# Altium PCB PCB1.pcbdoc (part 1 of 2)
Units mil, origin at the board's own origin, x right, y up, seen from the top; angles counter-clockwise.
Board outline 7352.2 x 4397.09 mil, 2 copper layers (Top Layer, Bottom Layer); 16 components, 5 nets, 164 pads, 4 vias.
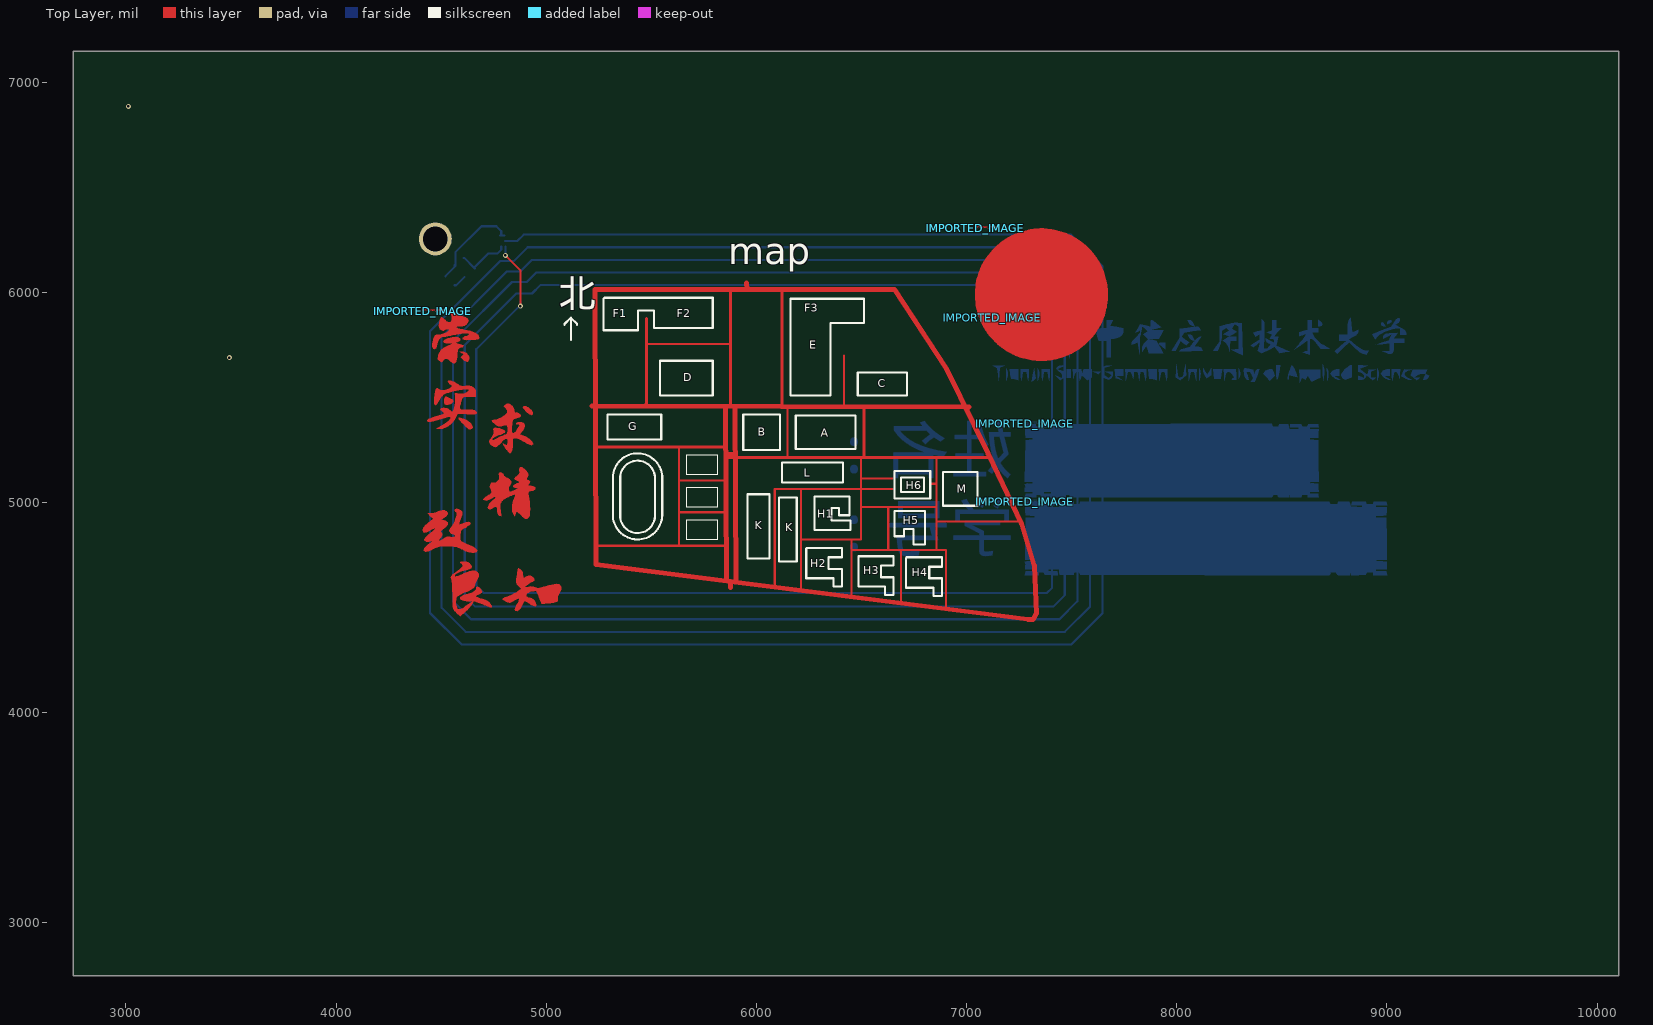
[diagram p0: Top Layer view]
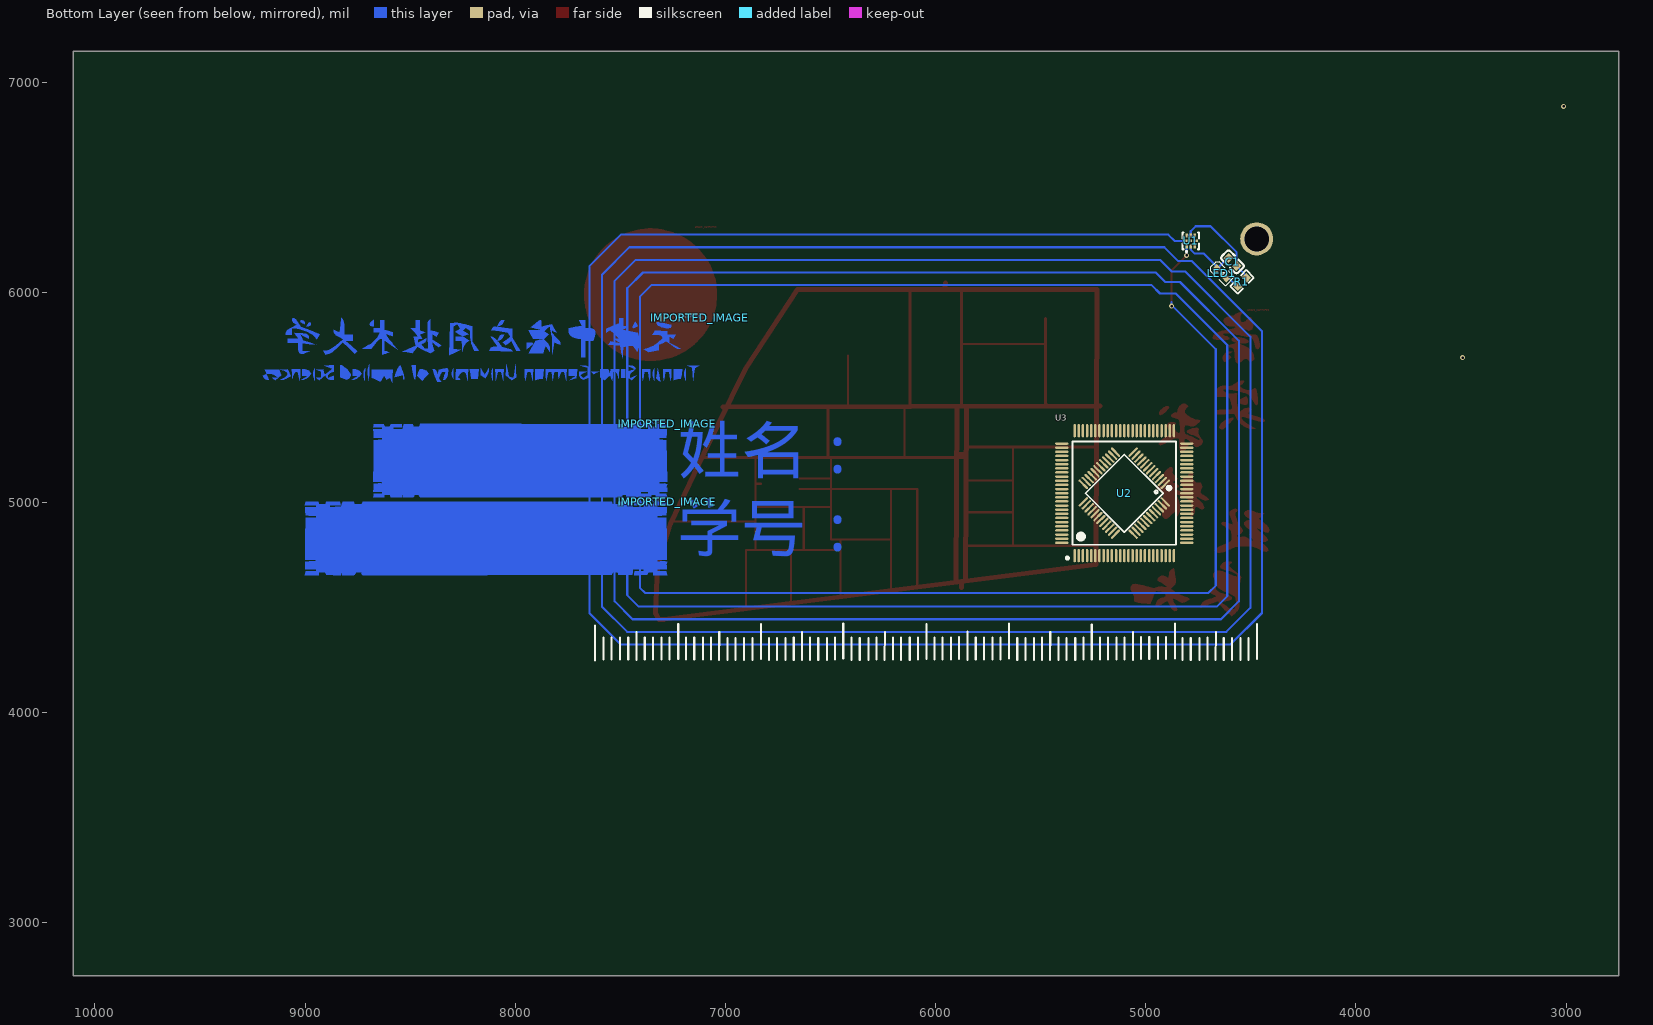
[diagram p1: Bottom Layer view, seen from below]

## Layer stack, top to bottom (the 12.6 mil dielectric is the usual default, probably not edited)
Top Solder: solder mask 0.4, Solder Resist, Dk 3.5
Top Layer: signal copper 1.4
Dielectric 1: dielectric 12.6, FR-4, Dk 4.8
Bottom Layer: signal copper 1.4
Bottom Solder: solder mask 0.4, Solder Resist, Dk 3.5

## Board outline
10102.2,2750 2750,2750 2750,7147.09 10102.2,7147.09

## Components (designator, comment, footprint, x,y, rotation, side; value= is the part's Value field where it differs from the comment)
C1 "100nF" C0603 4587.01,6145.08 r225 bottom
IMPORTED_IMAGE "IMPORTED_IMAGE" IMPORTED_IMAGE#1 7277.01,5005.08 r0 top
IMPORTED_IMAGE "IMPORTED_IMAGE" IMPORTED_IMAGE#1 4412.01,5910.08 r0 top
IMPORTED_IMAGE "IMPORTED_IMAGE" IMPORTED_IMAGE#2 4412.01,5910.08 r0 top
IMPORTED_IMAGE "IMPORTED_IMAGE" IMPORTED_IMAGE#3 7277.01,5005.08 r0 bottom
IMPORTED_IMAGE "IMPORTED_IMAGE" IMPORTED_IMAGE#4 7042.01,6305.08 r0 top
IMPORTED_IMAGE "IMPORTED_IMAGE" IMPORTED_IMAGE#1 7042.01,6305.08 r0 top
IMPORTED_IMAGE "IMPORTED_IMAGE" IMPORTED_IMAGE#5 7122.01,5880.08 r0 bottom
IMPORTED_IMAGE "IMPORTED_IMAGE" IMPORTED_IMAGE#1 7122.01,5880.08 r0 top
IMPORTED_IMAGE "IMPORTED_IMAGE" IMPORTED_IMAGE#6 7277.01,5375.08 r0 bottom
IMPORTED_IMAGE "IMPORTED_IMAGE" IMPORTED_IMAGE#1 7277.01,5375.08 r0 top
LED1 "LED_0603-R" LED_0603 4637.01,6090.08 r225 bottom
R1 "100" R0603 4542.01,6050.08 r315 bottom
U1 "NT3H1101W0FHKH" XQFN-8_L1.6-W1.6-P0.50-BR 4785.63,6245.08 r270 bottom
U2 "STM32F103C8T6" LQFP-48_L7.0-W7.0-P0.50-LS9.0-BL 5102.01,5045.08 r45 bottom
U3 "STM32F103VET6" LQFP-100_L14.0-W14.0-P0.50-LS16.0-BL 5102,5045.08 r180 bottom

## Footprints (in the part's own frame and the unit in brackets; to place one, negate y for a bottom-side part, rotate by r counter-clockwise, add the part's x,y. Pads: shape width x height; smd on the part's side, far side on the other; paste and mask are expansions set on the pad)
C0603 [mm]
  rect 0.8x0.9 smd: 1(-0.7,0) 2(0.7,0)
  silkscreen extent -1.41,-0.71 1.39,0.72
IMPORTED_IMAGE#1 [mil]
IMPORTED_IMAGE#2 [mil]
  Top Layer region: 241 vertices and 2 holes, not listed, extent 134.67,-1450 328.29,-1191.69
  Top Layer region: 207 vertices and 1 holes, not listed, extent 379.28,-1426.39 660.32,-1223.11
  Top Layer region: 243 vertices and 1 holes, not listed, extent 0,-1148.07 258.66,-939.82
  Top Layer region: 227 vertices and 4 holes, not listed, extent 288.06,-987.51 536.74,-741.06
  Top Layer region: 219 vertices and 0 holes, not listed, extent 316.84,-675.31 527.2,-439.17
  Top Layer region: 226.72,-561.52 225.26,-561.75 223.72,-561.67 222.08,-561.27 220.31,-560.53 218.36,-559.44 216.2,-557.97 213.8,-556.11 211.11,-553.84 208.11,-551.14 204.76,-548 201.02,-544.4 196.87,-540.32 186.69,-529.9 178.36,-520.66 172.73,-513.6 170.66,-509.73 172.72,-506.65 178.26,-506.16 186.33,-507.85 195.97,-511.33 206.23,-516.19 216.15,-522.04 224.8,-528.47 231.2,-535.1 236.73,-543.08 238.75,-548.58 237.35,-553.04 232.61,-557.9 231.06,-559.18 229.59,-560.22 228.15,-561
  Top Layer region: 233 vertices and 0 holes, not listed, extent 21.41,-559.62 257.78,-329.08
  Top Layer region: 517.83,-494.02 506.29,-488.89 491.8,-477.12 480.17,-464.21 477.18,-455.63 479.4,-453.03 481.81,-451.32 484.55,-450.55 487.76,-450.72 491.57,-451.88 496.12,-454.03 501.54,-457.22 507.98,-461.46 518.32,-471.31 524,-481.97 524.13,-490.52
  Top Layer region: 121.98,-444.16 116.46,-444.58 109.77,-443.89 105.54,-441.46 103.31,-436.83 102.64,-429.47 103.41,-417.6 105.38,-410.25 106.69,-408.49 108,-407.27 109.55,-406.61 111.59,-406.54 114.34,-407.07 118.05,-408.22 122.95,-410.03 129.28,-412.5 140.65,-418.84 145.38,-425.14 144.75,-428.85 142.96,-432.4 140.16,-435.69 136.51,-438.62 132.16,-441.07 127.26,-442.95
  Top Layer region: 147.64,-246.81 144.53,-246.1 141.17,-244.65 137.55,-242.46 133.69,-239.52 129.58,-235.83 124.6,-231.38 120.13,-228.17 116.04,-226.18 112.24,-225.41 108.6,-225.86 105,-227.52 101.33,-230.39 97.48,-234.46 92.72,-239.46 88.93,-241.21 84.76,-239.77 78.88,-235.18 75.81,-232.36 73.59,-229.71 72.21,-226.95 71.66,-223.82 71.93,-220.05 73.02,-215.38 74.9,-209.52 77.57,-202.22 80.32,-195.52 83.22,-189.79 86.43,-184.86 90.14,-180.55 94.51,-176.71 99.72,-173.14 105.93,-169.69 113.31,-166.17 139.97,-154.18 118.97,-152.43 109.89,-151.11 103.46,-149 99.67,-146.25 98.52,-143.03 99.99,-139.5 104.09,-135.83 110.79,-132.18 120.1,-128.71 140.39,-123.36 156.29,-121.45 168.15,-122.99 176.29,-127.98 178.49,-130.92 179.4,-133.8 179.03,-136.61 177.38,-139.35 174.45,-142.01 170.25,-144.59 164.77,-147.09 158.02,-149.51 155.9,-150.73 157.13,-151.79 161.38,-152.59 168.31,-153 196.42,-161.64 191.66,-169.91 185.05,-170.44 179.41,-172.05 174.7,-174.77 170.9,-178.64 167.99,-183.69 165.95,-189.95 164.74,-197.47 164.34,-206.27 164.2,-213.57 163.77,-220.16 163.07,-226.03 162.08,-231.17 160.82,-235.59 159.29,-239.29 157.49,-242.26 155.42,-244.5 153.09,-246 150.49,-246.77 hole: 45054399.35,57026498.92 45022991.2,56973466.69 45022991.2,56973466.69 45107494.63,56980418.58 45107494.63,56980418.58 45249793.81,57038162.49 45249793.81,57038162.49 45383706.76,57114557.03 45383706.76,57114557.03 45443051.52,57177460.84 45443051.52,57177460.84 45426988.58,57215262.03 45426988.58,57215262.03 45388369.6,57230983.63 45388369.6,57230983.63 45293492.32,57195011.68 45293492.32,57195011.68 45163367.65,57113598.68 45163367.65,57113598.68 45054399.35,57026498.92 hole: 45417340.55,56880426.7 45443051.52,56930568.26 45443051.52,56930568.26 45426756.88,56983881.35 45426756.88,56983881.35 45386771.99,57008723.03 45386771.99,57008723.03 45336445.35,57002362.21 45336445.35,57002362.21 45289125.48,56962067.76 45289125.48,56962067.76 45292169.77,56918080.94 45292169.77,56918080.94 45348598.63,56881390.8 45348598.63,56881390.8 45417340.55,56880426.7
  Top Layer region: 209.19,-238.8 204.28,-237.48 198.68,-234.57 192.45,-230.06 181.33,-218.58 187.64,-211.04 192.96,-207.29 194.52,-204.51 192.22,-201.82 185.93,-198.33 179.46,-194.9 177.49,-193.06 180.16,-192.28 187.59,-192.05 194.21,-192.61 200.45,-194.37 206.15,-197.17 211.17,-200.9 215.34,-205.4 218.51,-210.53 220.52,-216.17 221.23,-222.16 220.71,-228.53 219.18,-233.39 216.71,-236.73 213.36,-238.54
  Top Layer region: 171 vertices and 1 holes, not listed, extent 45.29,-179.59 268.64,0
IMPORTED_IMAGE#3 [mil]
  Top Layer region: 203 vertices and 22 holes, not listed, extent 0,0 1723.38,350.15
IMPORTED_IMAGE#4 [mil]
  Top Layer region: 269 vertices and 1 holes, not listed, extent 0,-629.92 629.92,0
  Top Layer region: 302.29,-590.54 302.11,-581.24 301.93,-571.94 297.84,-580.69 294.1,-586.88 290.88,-589.45 288.27,-586.74 286.04,-580.15 284.09,-573.58 282.18,-570.85 280.85,-573.06 280.29,-578.38 279.65,-584.09 278.09,-587.26 276.51,-586.13 275.9,-581 276.3,-574.58 277.27,-569.82 279.55,-567.44 283.19,-566.9 287.12,-569.28 289.77,-575.22 291.8,-582.88 295.28,-575.69 298.76,-568.51 318.67,-569.13 338.57,-569.75 338.63,-580.15 338.2,-587.49 337.06,-590.54 335.22,-589.26 333.07,-586.17 330.79,-583.07 328.6,-581.79 327.1,-583.07 326.48,-586.17 325.83,-589.26 324.28,-590.54 322.72,-588.08 322.08,-582.15 321.74,-575.89 320.93,-572.62 318.51,-572.11 314.33,-572.51 310.48,-573.81 308.88,-575.48 309.85,-576.84 312.18,-577.41 314.51,-577.98 315.48,-579.35 314.04,-581.09 310.57,-582.56 307.5,-584.03 307.82,-585.88 310.64,-587.64 314.38,-588.98 315.14,-589.8 310.53,-590.29 hole: 73698232.4,57263164.84 73722373.94,57250212.95 73722373.94,57250212.95 73743248,57269498.12 73743248,57269498.12 73753922.96,57296943.63 73753922.96,57296943.63 73752029.44,57318555.91 73752029.44,57318555.91 73738673.92,57330884.64 73738673.92,57330884.64 73721790.32,57336012.93 73721790.32,57336012.93 73703751.04,57329024.48 73703751.04,57329024.48 73687616.82,57312222.62 73687616.82,57312222.62 73684640.47,57287997.37 73684640.47,57287997.37 73698232.4,57263164.84
  Top Layer region: 357.1,-586.3 352.05,-587.98 346.86,-587.75 343.25,-586.19 342.52,-584.38 346.27,-584.38 350.34,-584.22 352.4,-582.88 351.5,-581.13 348.42,-579.98 344.81,-578.56 342.6,-576.15 342.13,-572.99 342.67,-569.75 345.16,-567.43 349.37,-566.47 353.61,-567.11 356.17,-568.66 355.52,-570.22 351.9,-570.85 347.92,-571.41 346.27,-572.76 348.25,-574.51 353.02,-576.02 358.31,-578.07 359.07,-582.31
  Top Layer region: 267.17,-586.17 265.09,-584.08 262.69,-579.05 260.06,-571.94 257.9,-577.96 255.89,-582.21 254.1,-583.98 253.61,-580.76 254.72,-573.04 257.09,-565.31 259.62,-562.09 262.24,-564.18 264.83,-569.21 267.39,-576.32 270.51,-569.75 273.64,-563.19 272.4,-570.85 271.21,-577.38 270.08,-582.34 268.78,-585.04
  Top Layer region: 367.59,-583.5 366.38,-586.17 364.59,-584.16 363.04,-579.33 362.07,-573.38 361.66,-568.68 362.32,-566.74 364.51,-565.1 368.57,-563.61 374.83,-562.1 385.89,-560.45 391.14,-561.92 393.94,-563.1 395.72,-560.02 396.95,-556.85 397.92,-555.53 398.43,-559.06 398.58,-567.56 397.94,-576.06 396.56,-579.6 395.21,-578.64 394.65,-576.32 393.36,-572.71 390.25,-568.66 386.11,-565.57 382.31,-564.28 379.7,-566.13 380.24,-574.13 380.74,-581.38 379.48,-583.98 377.18,-581.36 374.82,-575.08 372.35,-568.93 369.79,-567.11 368.03,-570.24 367.75,-577.1
  Top Layer region: 246.26,-580.37 242.88,-580.82 238.87,-580.33 235.41,-578.68 233.33,-576.36 233.24,-571.74 234.54,-564.57 236.71,-558.57 238.71,-556.75 239.64,-560.5 239.22,-567.88 238.75,-576.09 241.95,-577.07 245.49,-574.38 247.99,-568.1 249.95,-562.31 251.92,-559.9 253.32,-560.77 253.9,-562.86 253.21,-566.92 251.55,-572.53 249.03,-577.61
  Top Layer region: 216.91,-572.54 214.99,-571.15 214.32,-565.56 213.77,-560.02 212.47,-557.72 210.39,-559.41 207.99,-563.47 205.76,-567.17 204.11,-567.98 204.36,-564.15 206.71,-556.68 210.12,-549.81 212.89,-547.4 215.12,-550.15 217.23,-555.68 219.28,-561.45 221.51,-558.26 223.64,-554.79 225.56,-553.34 225.66,-556.03 223.42,-562.51 219.89,-569.24
  Top Layer region: 421.33,-570.85 417.86,-569.78 414.07,-567.23 411.23,-562.87 410.05,-557.49 411.14,-552.47 413.9,-549.14 417.1,-547.54 419.39,-546.84 421.85,-548.08 425.44,-551.15 428.55,-555.72 429.84,-560.56 429.06,-564.89 427.2,-568.22 424.39,-570.08 hole: 74631321.42,57383648.24 74657526.37,57388368.39 74657526.37,57388368.39 74667450.02,57412441.27 74667450.02,57412441.27 74660762.78,57450208.73 74660762.78,57450208.73 74644683.81,57490640.05 74644683.81,57490640.05 74622169.97,57520536.31 74622169.97,57520536.31 74600009.09,57532970.63 74600009.09,57532970.63 74580480.94,57522453.91 74580480.94,57522453.91 74564296.14,57497170.29 74564296.14,57497170.29 74561111.14,57461509.18 74561111.14,57461509.18 74572840.07,57426046.67 74572840.07,57426046.67 74599238.82,57399020.79 74599238.82,57399020.79 74631321.42,57383648.24
  Top Layer region: 200.91,-560.1 199.95,-563.99 198.14,-563.35 195.39,-560.23 191.76,-556.87 187.74,-556.68 184.77,-557.28 183.53,-556.85 185.55,-553.73 190.43,-547.86 196.02,-542.59 199.77,-540.91 201.38,-544.46 201.65,-552.32 hole: 72354289.42,57511086.44 72375065.35,57517942.21 72375065.35,57517942.21 72392172.99,57534425.93 72392172.99,57534425.93 72399454.85,57553852.25 72399454.85,57553852.25 72396604.4,57567781.81 72396604.4,57567781.81 72381325.39,57565057.23 72381325.39,57565057.23 72358723.03,57544442.33 72358723.03,57544442.33 72344532.36,57519964.86 72344532.36,57519964.86 72354289.42,57511086.44
  Top Layer region: 439.73,-561.12 438.73,-563.13 435.91,-561.48 432.12,-555.69 428.96,-548.95 427.64,-545.01 429.09,-542.94 432.59,-540.69 436.57,-538.97 439.19,-538.17 440.35,-538.71 440.84,-540.21 439.87,-541.75 437.54,-542.4 435.21,-543.44 434.24,-545.94 435.29,-548.35 438.64,-548.33 441.74,-548.12 443.04,-549.24 442.08,-551.05 439.78,-552.53 437.72,-554.39 438.68,-557.8
  Top Layer region: 178.58,-555.51 177.42,-554.86 176.93,-553.26 177.97,-550.08 180.48,-545.6 182.37,-541.79 181.92,-540.21 179.26,-541.49 175.83,-544.59 172.4,-547.68 169.75,-548.96 168.65,-546.65 169.1,-540.76 170.56,-532.55 165.03,-539.11 161.1,-543.2 159.42,-543.79 160.78,-539.93 164.18,-533.32 168.64,-527.26 172.43,-525.43 174.88,-527.68 175.07,-533.69 174.99,-539.72 178.54,-537.46 182.25,-534.76 185.22,-533.64 187.34,-534.27 188.99,-535.78 188.45,-539.87 185.27,-546.7 181.23,-552.92
  Top Layer region: 460.87,-547.07 459.06,-550.37 457.74,-548.96 456.25,-544.48 454.25,-538.32 452.93,-532.55 453.09,-529.02 454.29,-527.65 455.49,-527.08 458.86,-529.06 465.27,-533.84 471,-539.13 472.73,-542.38 470.66,-543.31 467.25,-543.04 463.42,-543.34 hole: 75019323.4,57631449.49 75034855.31,57647050.73 75034855.31,57647050.73 75041315.49,57665566.94 75041315.49,57665566.94 75034855.31,57680111.17 75034855.31,57680111.17 75019323.4,57686159.96 75019323.4,57686159.96 75003791.49,57676137.55 75003791.49,57676137.55 74997331.31,57652042.51 74997331.31,57652042.51 75003791.49,57631919.45 75003791.49,57631919.45 75019323.4,57631449.49
  Top Layer region: 479.55,-536.27 478.94,-538.76 476,-537.09 470.87,-531.13 464.2,-522.1 469.37,-517.93 474.05,-515.18 478.03,-514.42 480.71,-516.63 482.22,-521.08 482,-525.4 480.33,-527.08 478.78,-528.45 479.04,-532.22 hole: 75151641.53,57777131.72 75171805.53,57783739.37 75171805.53,57783739.37 75188370.52,57803190.04 75188370.52,57803190.04 75195260.09,57829698.36 75195260.09,57829698.36 75188597.31,57851970.45 75188597.31,57851970.45 75172577.45,57861233.48 75172577.45,57861233.48 75152733.72,57851313.65 75152733.72,57851313.65 75136873.3,57827463.99 75136873.3,57827463.99 75131274.11,57800032.97 75131274.11,57800032.97 75136099.18,57781502.81 75136099.18,57781502.81 75151641.53,57777131.72
  Top Layer region: 153.18,-537.2 152.04,-534.69 152.19,-530.41 152.35,-526.51 151.24,-524.89 149.05,-525.65 146.62,-527.48 144.38,-528.91 142.66,-528.72 143.32,-525.63 146.82,-520.11 152.35,-512.85 147.18,-509.02 142.97,-506.77 140.59,-507.48 140.4,-510.07 141.94,-513.09 143.19,-515.57 138.83,-514.94 134.67,-514.41 132.95,-515.18 134.02,-517.56 136.59,-520.89 138.57,-523.69 138.24,-524.82 135.27,-523.48 130.95,-520.36 125.65,-515.97 133.03,-508.39 138.54,-503.04 141.42,-500.82 142.74,-501.53 145.59,-503.47 149.54,-506.34 154.19,-509.84 162.75,-517.58 165.93,-523.17 164.71,-526.55 161.74,-528.58 158.44,-530.64 156.39,-534.07 154.97,-536.8 hole: 71963691.83,57812951.48 71994267.98,57798962.02 71994267.98,57798962.02 72020706.04,57801027.88 72020706.04,57801027.88 72023612.02,57820846.21 72023612.02,57820846.21 72005139.22,57843862.9 72005139.22,57843862.9 71974563.07,57857852.37 71974563.07,57857852.37 71948125.01,57855786.5 71948125.01,57855786.5 71945219.03,57835968.18 71945219.03,57835968.18 71963691.83,57812951.48
  Top Layer region: 337 vertices and 0 holes, not listed, extent 103.23,-529.56 518.83,-113.73
  Top Layer region: 496.4,-528.17 488.41,-520.63 482.77,-514.61 480.42,-510.71 482.27,-507.94 486.71,-504.63 491.67,-502.48 494.76,-502.52 495.59,-502.51 495.14,-500.27 494.88,-497.46 496.6,-496.44 500.13,-498.05 504.61,-501.91 509.6,-506.03 513.79,-503.76 516.91,-501.59 517.81,-503.04 516.73,-506.28 514.13,-509.99 510.1,-512.67 504.23,-508.11 498.02,-502.19 498.02,-507.94 497.37,-512.4 495.81,-515.05 494.66,-517.73 495,-522.29 hole: 75305115.51,57910429.68 75327212.6,57915943.95 75327212.6,57915943.95 75342744.51,57931545.19 75342744.51,57931545.19 75349204.69,57950061.4 75349204.69,57950061.4 75339895.99,57964605.64 75339895.99,57964605.64 75317514.09,57970654.43 75317514.09,57970654.43 75291416.36,57964670.2 75291416.36,57964670.2 75273171.45,57950282.43 75273171.45,57950282.43 75270801.25,57931856.49 75270801.25,57931856.49 75282869.96,57916164.98 75282869.96,57916164.98 75305115.51,57910429.68
  Top Layer region: 122.6,-510.49 117.77,-507.12 114.3,-502.44 114.04,-497.59 113.94,-493.02 111.29,-489.08 108.09,-486.92 106.02,-486.77 103.76,-486.95 100.15,-485.6 96.91,-482.5 95.56,-478.48 96.63,-474 99.2,-469.8 103.21,-466.98 107.73,-465.8 112,-466.79 115.41,-469.15 117.09,-472.98 115.61,-478.16 114.14,-483.3 114.26,-487.72 116.44,-490.5 122.02,-489.18 127.95,-487.88 132.05,-490.23 134.22,-493.91 134.49,-497.82 133.33,-500.45 131.82,-496.99 129.91,-493.51 127.53,-492.06 124.49,-493.31 120.98,-496.3 118.68,-499.98 118.57,-502.87 120.15,-504.51 121.92,-505.19 123.48,-504.13 124.54,-501.57 125.59,-499.11 127.99,-501.24 129.42,-504.59 126.74,-508.13 hole: 71418885.46,58218850.41 71443498.18,58211380.51 71443498.18,58211380.51 71474797.31,58223832.07 71474797.31,58223832.07 71510332.13,58253770.19 71510332.13,58253770.19 71533314.13,58290540.55 71533314.13,58290540.55 71534433.25,58319422.76 71534433.25,58319422.76 71518866.98,58335851.77 71518866.98,58335851.77 71501728.82,58342685.65 71501728.82,58342685.65 71474169.99,58330870.1 71474169.99,58330870.1 71433551.16,58302462.51 71433551.16,58302462.51 71402526.92,58266492.29 71402526.92,58266492.29 71399423.84,58236809.94 71399423.84,58236809.94 71418885.46,58218850.41
  Top Layer region: 171 vertices and 10 holes, not listed, extent 182.17,-507.46 440.54,-185.69
  Top Layer region: 523.05,-499.05 521.11,-499.66 518.16,-498.29 514.15,-495.11 509.63,-491.3 506.52,-487.75 505.91,-485.18 509.26,-485.88 515.67,-490.19 521.39,-495.63
  Top Layer region: 532.54,-488.46 527.67,-494.54 519.05,-487.12 510.42,-479.7 514.67,-473.92 518.15,-469.81 520.56,-468.06 521.72,-468.34 522.21,-469.12 521.42,-471.16 519.54,-474.49 518.13,-477.95 518.48,-480.33 520.37,-480.69 522.68,-479.33 525.12,-477.51 527.31,-476.74 527.97,-477.68 526.69,-479.93 525.25,-482.9 525.53,-485.55 527.7,-486.46 531.24,-484.2 534.49,-481.82 536.42,-481.4 535.69,-483.88
  Top Layer region: 543,-474.03 539.6,-478.86 530.9,-473.14 524.76,-468.53 522.21,-465.51 523.5,-462.89 526.6,-459.24 530.68,-456.15 534.3,-454.86 537.92,-456.15 542,-459.24 545.11,-463.15 546.4,-466.41 545.4,-469.8 hole: 75809008.63,58320801.46 75825974.42,58333432.47 75825974.42,58333432.47 75833030.58,58363799.52 75833030.58,58363799.52 75820534.95,58400822.64 75820534.95,58400822.64 75790491.29,58429452.09 75790491.29,58429452.09 75758086.5,58445452.17 75758086.5,58445452.17 75739909.49,58452106.6 75739909.49,58452106.6 75726817.6,58444730.81 75726817.6,58444730.81 75706633.27,58426996.68 75706633.27,58426996.68 75698181.43,58398523.16 75698181.43,58398523.16 75733193.11,58361344.11 75733193.11,58361344.11 75776829.26,58332711.11 75776829.26,58332711.11 75809008.63,58320801.46
  Top Layer region: 320.17,-474.7 318.23,-476.2 316.24,-475.54 315.48,-472.37 316.24,-469.19 318.23,-468.54 320.17,-470.04 320.98,-472.37
  Top Layer region: 91.59,-470.09 88.19,-470.87 88.24,-467.75 90.13,-462.01 92.23,-455.91 90.05,-455.73 86.6,-457.08 82.91,-458.49 80.65,-459.01 80.61,-458.23 83.83,-455.53 89.41,-451.42 95.01,-447.79 98.31,-446.21 99.47,-447.15 99.96,-449.53 99.29,-453.2 97.68,-457.19 96.53,-460.51 98.34,-461.43 101.19,-460.65 103.92,-458.8 105.87,-457.46 106.56,-458.51 104.04,-461.81 98,-466.48
  Top Layer region: 302.09,-467.02 299.73,-467.38 297.4,-466.2 296.16,-463.58 296.41,-460.52 298.31,-458.45 301.1,-458.41 303.49,-460.18 304.48,-462.63 303.78,-465.12
  Top Layer region: 321.11,-463.01 318.78,-463.61 316.45,-463.08 315.48,-461.79 315.89,-460.09 316.89,-458.57 318.44,-457.92 320.19,-458.33 321.52,-459.76 322.08,-461.56
  Top Layer region: 557.15,-451.04 553.8,-452.67 551.34,-451.97 554.11,-448.28 556.56,-444.81 556.84,-442.64 554.3,-442.82 549.98,-445.03 545.36,-447.19 542.1,-447.26 540.47,-444.8 539.8,-440.87 540.23,-436.93 541.27,-434.44 542.84,-433.41 544.57,-432.98 545.86,-433.62 546.4,-435.16 545.75,-436.71 544.2,-437.35 542.65,-438 542,-439.54 542.97,-441.09 545.3,-441.73 547.63,-441.16 548.6,-439.78 549.68,-437.98 552.29,-436.41 555.86,-436.36 559.27,-438.29 561.42,-442.02 560.03,-447.12
  Top Layer region: 79.82,-451.27 76.29,-451.73 75.67,-450.6 75.95,-449.64 78.86,-447.69 84.56,-444.18 90.48,-440.91 93.91,-439.55 95.08,-440.17 95.56,-441.69 92.91,-444.54 86.55,-448.4
  Top Layer region: 78.77,-443.24 75.18,-443.56 71.62,-442.4 68.91,-439.14 67.37,-434.4 67.57,-430.3 69.02,-428.6 70.68,-430.26 71.37,-434.25 72.09,-438.17 74.12,-438.95 75.85,-437.15 76.17,-434.17 76.02,-430.56 76.65,-427.28 78.77,-425.12 82.22,-424.22 86.05,-425.58 89.09,-428.83 90.45,-432.94 89.17,-435.84 87.31,-436.58 86.76,-433.41 86.12,-430.01 84.56,-428.6 83.01,-430.55 82.36,-435.23 81.4,-440.46
  Top Layer region: 563.88,-434.11 559.13,-434.15 553.99,-432.01 550.13,-428.08 548.6,-423.52 549.37,-419.23 551.24,-415.91 553.94,-414.05 556.73,-413.28 558.75,-413.92 559.59,-415.47 558.66,-417.01 556.42,-417.66 553.73,-418.4 551.69,-420.18 551.78,-422.82 554.18,-425.65 558.21,-427.73 562.21,-428.6 565.27,-427.24 566.19,-422.69 566.74,-418.64 568.67,-419.25 570.02,-422.6 569.76,-427.2 567.46,-431.49
  Top Layer region: 58.85,-419.06 59.24,-416.57 62.2,-412.58 65.57,-408.23 66.97,-404.86 66.02,-403.29 62.72,-404.45 58.92,-406.05 55.75,-406.72 54.32,-406.23 54.67,-405.07 57.87,-403.16 63.28,-400.86 69.02,-399 73.02,-398.13 74.96,-398.9 75.77,-400.98 74.8,-403.91 72.47,-406.72 70.14,-409.19 69.17,-411.31 70.78,-412.01 74.67,-411.09 78.59,-410.17 80.17,-410.97 77.24,-413.46 70.22,-416.7 62.78,-418.95
  Top Layer region: 573.41,-415.47 569.54,-414.42 562.46,-411.91 556.16,-408.87 554.18,-406.58 557.85,-406.32 565.13,-408.16 572.09,-411.1 574.99,-413.49 574.52,-414.89
  Top Layer region: 579.41,-403.4 578.33,-406.31 574.69,-406.21 567.35,-404.54 560.32,-402.03 557.39,-399.9 558.17,-395.7 560.03,-388.22 563.34,-380.05 568.82,-377.08 573.18,-375.53 574.99,-373.72 573.7,-372.29 570.59,-371.7 567.48,-370.98 566.19,-369.26 567.53,-367.86 571.14,-368.22 576.41,-369.59 582.13,-370.93 586.41,-372.37 588.18,-373.98 585.44,-376.16 578.84,-378.97 569.49,-382.23 576.64,-383.81 581.68,-385.55 583.78,-387.53 582.06,-388.66 577.74,-388.25 572.41,-386.92 568.11,-385.76 565.09,-386.37 563.35,-390.79 562.84,-395.4 563.27,-397.96 564.86,-397.6 567.16,-395.22 569.61,-392.52 571.53,-391.4 572.24,-392.63 571.75,-395.59 571.44,-398.94 572.59,-401.13 575.17,-400.29 578.3,-396.39 581.83,-390.3 580.58,-397.8
  Top Layer region: 58.58,-397.27 53.96,-397.95 52.24,-397.48 52.47,-396.32 55.67,-394.41 61.08,-392.11 66.82,-390.25 70.82,-389.37 72.76,-389.87 73.57,-391.29 71.15,-393.44 65.32,-395.66
  Top Layer region: 321.94,-392.11 313.2,-393.59 305.08,-392.65 298.1,-390.41 292.63,-386.48 288.13,-381.46 285.42,-374.57 284.33,-366.08 285.54,-357.18 289.18,-349.69 293.98,-344.35 298.71,-341.03 304.83,-339.66 312.99,-339.01 318.32,-339.24 322.46,-340.42 326.47,-343.06 331.41,-347.65 336.34,-352.81 338.85,-356.78 339.56,-361.2 339.13,-367.75 338.27,-373.82 336.77,-378.33 334.19,-382.2 330.09,-386.34 hole: 73528358.93,59196864.97 73589794.37,59205187.8 73589794.37,59205187.8 73635728.69,59224220.2 73635728.69,59224220.2 73668478.21,59258189.39 73668478.21,59258189.39 73698219.2,59302423.36 73698219.2,59302423.36 73714295.14,59360109.81 73714295.14,59360109.81 73711929.07,59427629.37 73711929.07,59427629.37 73688021.75,59489478.74 73688021.75,59489478.74 73650043.34,59534745.91 73650043.34,59534745.91 73594676.89,59558373.18 73594676.89,59558373.18 73528963.71,59568200.27 73528963.71,59568200.27 73460704.4,59554646.57 73460704.4,59554646.57 73401904.43,59514485.53 73401904.43,59514485.53 73360939.23,59454773.15 73360939.23,59454773.15 73347924.86,59382184.66 73347924.86,59382184.66 73360939.23,59309596.17 73360939.23,59309596.17 73401904.43,59249883.79 73401904.43,59249883.79 73460511.69,59209781.84 73460511.69,59209781.84 73528358.93,59196864.97
  Top Layer region: 52.66,-388.66 49.14,-386.71 47.79,-384.13 47.21,-382.1 47.78,-380.94 49.19,-380.45 50.86,-381.19 52.05,-382.96 54.54,-384.3 61.18,-382.74 67.37,-381.16 70.64,-381.18 71.07,-382.64 70.48,-384.5 66.88,-386.46 60.09,-388.16
  Top Layer region: 48.97,-377.18 47.18,-375.62 48.58,-372.34 51.96,-368.01 56.74,-362.95 50.31,-362.79 45.77,-362.34 48.28,-360.76 53.48,-359.39 59.82,-358.72 64.87,-359.2 66.97,-360.58 65.19,-363.31 60.92,-367.07 54.87,-371.56 62.57,-371.77 67.82,-372.28 65.87,-373.7 60.66,-375.31 54.32,-376.79
  Top Layer region: 317.7,-371.68 312.42,-372.8 307.24,-371.73 303.75,-369.15 302.64,-365.52 304.42,-361.93 308.18,-359.55 313.09,-359.01 317.7,-360.79 318.78,-366.23
  Top Layer region: 585.55,-365.91 581.22,-367.15 575.65,-366.11 570.72,-363.02 568.76,-357.67 569.09,-352.66 570.96,-349.54 573.51,-348.23 575.54,-347.66 576.7,-348.05 577.19,-349.03 576.06,-350.89 573.34,-353.41 570.68,-356.44 573.85,-359.73 577.9,-361.89 581.54,-362.38 583.91,-360.29 584.45,-355.61 584.81,-351.34 586.65,-350.4 588.51,-352.82 589.28,-357.42 588.19,-362.45
  Top Layer region: 53.78,-353.57 44.99,-356.64 42.78,-355.1 43.43,-352.91 44.98,-352.01 46.53,-351.02 47.18,-348.65 46.21,-345.92 43.88,-344.04 41.55,-342.51 40.58,-340.59 42.82,-339.38 48.83,-339.84 55.78,-341.2 60.92,-342.42 63.64,-344.01 64.77,-346.25 61.54,-349.51 hole: 70933790.35,59555834.07 70952307.13,59558192.63 70952307.13,59558192.63 70966765.83,59569919.55 70966765.83,59569919.55 70972779.57,59580433.54 70972779.57,59580433.54 70962707.74,59587249.91 70962707.74,59587249.91 70938493.9,59590084.46 70938493.9,59590084.46 70918336.51,59583551.49 70918336.51,59583551.49 70918021.47,59567843.56 70918021.47,59567843.56 70933790.35,59555834.07
  Top Layer region: 587.75,-346.85 582.4,-345.89 576.64,-345.47 571.57,-344.2 570.59,-337.78 571.23,-332.37 572.76,-330.12 574.14,-331.5 574.41,-334.8 574.85,-338.4 576.64,-340.46 578.62,-339.89 579.39,-336.87 580.03,-333.65 581.59,-332.31 583.14,-333.59 583.78,-336.69 584.43,-339.78 585.98,-341.06 587.6,-340.26 588.39,-338.33 588.73,-333.66 589.28,-326.29 589.16,-319.72 587.92,-316.99 585.86,-318.6 583.78,-322.46 581.06,-326.44 577.28,-327.93 573.66,-326.55 571.52,-322.59 570.99,-318.13 571.61,-314.93 573.14,-313.29 574.81,-312.61 575.78,-314.38 575.64,-318.63 575.29,-323.21 578.07,-320.27 581.12,-316.4 583.73,-313.24 586.28,-311.72 589.22,-311.8 591.86,-313.88 593.74,-317.17 594.2,-320.87 593.45,-323.93 592.45,-328.95 592.33,-337.37 592.03,-346.47
  Top Layer region: 348.97,-345.44 347.02,-344.48 345.47,-342.16 344.8,-339.84 344.97,-338.87 346.31,-339.84 348.47,-342.16 349.8,-344.51
  Top Layer region: 373.77,-340.26 369.66,-341.06 365.41,-340 361.29,-337.44 358.45,-333.09 357.27,-327.72 358.56,-322.33 362.15,-318.21 366.46,-315.8 369.95,-314.8 373.63,-316.42 378.4,-320.31 382.35,-325.68 382.47,-330.7 380.41,-334.96 377.52,-338.33 hole: 74067423.17,59709962.5 74107707.45,59699505.41 74107707.45,59699505.41 74147987.05,59705991.07 74147987.05,59705991.07 74172749.04,59721584.37 74172749.04,59721584.37 74178352.35,59749979.11 74178352.35,59749979.11 74172566.51,59787236.94 74172566.51,59787236.94 74151056.32,59818010.76 74151056.32,59818010.76 74118859.64,59830810.55 74118859.64,59830810.55 74083380.9,59821982.19 74083380.9,59821982.19 74053985.18,59800756.99 74053985.18,59800756.99 74040316.27,59769076.35 74040316.27,59769076.35 74042648.26,59735104.42 74042648.26,59735104.42 74067423.17,59709962.5
  Top Layer region: 62.57,-334.08 51.57,-334.83 43.17,-334.77 40.58,-332.86 42.92,-330.84 49.54,-330.12 56.63,-329.39 57.73,-326.29 55.51,-323.37 50.07,-322.46 44.7,-321.98 41.5,-320.82 42.72,-319.66 47.98,-319.18 54.33,-318.32 57.38,-315.9 58.85,-313.58 60.61,-312.61 61.99,-315.77 62.57,-323.34
  Top Layer region: 544.08,-285.33 541.99,-285.95 540.3,-285.4 539.28,-282.72 538.8,-278.25 537.62,-273.61 533.42,-272.1 528.83,-270.64 525.18,-267.67 523.12,-264.14 522.36,-261.31 523.03,-258.39 524.41,-254.62 525.98,-252.35 526.45,-257.28 527.67,-263.15 531.05,-266.68 534.88,-267.93 537.86,-267.59 539.2,-264.87 539.12,-260.38 537.85,-254.77 536.36,-249.35 535.7,-245.75 537.09,-245.55 539.21,-248.66 540.99,-254.1 542.37,-259.62 543.55,-262.93 545.19,-263.42 547.68,-262.13 549.75,-258.01 549.65,-250.53 548.53,-241.49 551.92,-250.19 554.94,-256.96 557.45,-261.02 558.96,-263.28 559.59,-265.7 558.13,-267.25 554.35,-267.24 550.11,-267.37 547.32,-269.12 546.2,-272.9 545.99,-277.94 545.62,-282.56
  Top Layer region: 73.8,-282.26 72.24,-285.67 69.69,-282.56 66.98,-273.26 63.68,-262.24 58.8,-258.68 54.3,-258.47 50.98,-259.81 48.71,-261.56 46.74,-262.28 45.5,-259.75 44.98,-253.68 45.97,-246.56 48.43,-241.65 51.47,-239.22 53.93,-238.21 55.37,-239.81 55.97,-243.68 56.6,-247.54 58.1,-249.15 60.29,-247.86 62.57,-244.77 64.78,-241.68 66.79,-240.4 68.43,-241.63 69.76,-244.6 72.05,-247.73 78.55,-247.08 84.71,-245.41 88.72,-243.83 91.45,-240.87 94.53,-235.88 97.89,-231.34 101.26,-229.45 103.56,-230.55 103.12,-234.38 100.78,-239.62 97.32,-245.33 91.59,-250.47 82.99,-253.87 75.12,-256.46 77.09,-259.35 81.82,-262.88 87.31,-267.19 91.58,-271.46 93.36,-274.84 92.84,-276.79 91.57,-277.6 88.45,-275.67 83.46,-271.03 78.42,-266.4 75.17,-264.47 74,-267.46 73.94,-274.65
  Top Layer region: 573.7,-276.94 570.59,-277.6 567.41,-276.8 565.93,-274.86 565.85,-272.15 566.01,-269.46 564.94,-265.01 561.87,-258.06 558.71,-250.29 557.39,-243.87 556.26,-239.37 553.55,-236.19 551.95,-234.42 557.39,-234.07 562.02,-234.47 562.34,-235.28 560.4,-236.99 559.59,-239.54 560.2,-241.96 561.85,-246.23 564.3,-251.75 567.29,-257.9 572.73,-269.3 574.99,-275.36
  Top Layer region: 591.35,-271.4 589.56,-272.82 585.29,-272.06 580.82,-269.06 577.93,-265.82 577.46,-264.47 580.54,-265.57 586.2,-268.23
  Top Layer region: 583.78,-257.9 580.89,-257.26 580.49,-255.71 582.02,-254.17 583.78,-253.53 585.55,-254.17 587.08,-255.71 586.67,-257.26
  Top Layer region: 275.22,-255.13 271.76,-257.12 268.19,-257.11 265.87,-255.34 265.43,-253.04 267.63,-250.77 271.66,-249.07 275.66,-248.74 277.8,-249.77 277.37,-252.17
  Top Layer region: 577.39,-242.42 574.33,-243.46 571.34,-243.24 569.26,-241.8 568.39,-239.93 569.41,-238.77 571.87,-239.07 575.08,-240.02 577.92,-240.43 578.96,-240.98
  Top Layer region: 536.45,-218.51 533.54,-217.06 531.27,-213.59 529.55,-207.33 527.97,-199.2 527.44,-192.48 528.75,-191.12 530.34,-192.89 531,-195.2 532.3,-199.62 535.4,-206.48 538.51,-213.05 539.8,-216.79 538.82,-218
  Top Layer region: 110.08,-217.58 109.26,-218.51 107.31,-217.55 105.76,-215.23 105.09,-212.91 105.26,-211.95 106.6,-212.91 108.76,-215.23
  Top Layer region: 98.21,-212.53 99.41,-214.13 96.12,-212.79 90.19,-209.54 84.66,-206.04 82.36,-204.07 82.89,-203.45 84.14,-203.19 87.58,-204.8 93.36,-208.66
  Top Layer region: 86.06,-196.41 84.3,-193.34 83.17,-186.34 83.39,-178.7 83.57,-172.45 82.12,-169.12 79.83,-168.95 77.75,-170.63 76.21,-172.29 75.8,-169.93 74.65,-166.59 71.92,-163.81 69.5,-162.02 72.71,-162.65 76.83,-162.64 80.12,-160.57 83.31,-158.21 87.07,-157.24 90.14,-158.32 89.87,-162.71 89.51,-166.63 90.74,-168.18 92.66,-167.37 94.1,-165.44 94.94,-164.96 95.39,-167.63 96.7,-171.5 101.06,-172.55 104.94,-173.2 106.56,-174.74 107.25,-176.29 108.9,-176.93 110.18,-175.68 109.85,-172.55 109.28,-169.46 109.85,-168.18 112.12,-168.86 115.6,-170.5 118.54,-173.25 118.67,-176.87 119.25,-180.61 125.16,-183.47 130.66,-185.83 132.95,-187.93 130.68,-188.34 125.23,-186.63 118.23,-184.75 112.25,-184.74 107.7,-184.83 104.78,-182.14 102.34,-179.48 99.07,-181.13 96.18,-182.68 95.56,-179.26 94.91,-176.28 93.36,-175.84 91.81,-176.11 91.16,-174.87 90.52,-173.24 88.96,-172.55 87.35,-176.57 86.57,-186.23 hole: 71224382.78,61389944.99 71247680.64,61384588.02 71247680.64,61384588.02 71270978.51,61394230.74 71270978.51,61394230.74 71280668.77,61417414.3 71280668.77,61417414.3 71275285.38,61440597.87 71275285.38,61440597.87 71262342.77,61450240.59 71262342.77,61450240.59 71245091.62,61445954.84 71245091.62,61445954.84 71229354.64,61435650.4 71229354.64,61435650.4 71218999.39,61419990.62 71218999.39,61419990.62 71214692.51,61402824.11 71214692.51,61402824.11 71224382.78,61389944.99
  Top Layer region: 73.47,-196.35 71.52,-195.62 69.86,-193.92 69.17,-191.85 70.06,-190.88 72.52,-192.29 74.59,-194.54 74.87,-196.06
  Top Layer region: 548.69,-187.87 547.07,-187.16 546.4,-185.43 545.59,-184.42 543.08,-183.93 538.77,-183.94 532.56,-184.46 520.25,-184.92 514.41,-181.1 510.11,-176.25 515.98,-180.01 522.31,-182.56 529.72,-182.29 535.29,-180.7 537.6,-178.93 535.18,-176.32 529.35,-172.7 524.51,-169.62 524.45,-168.27 529.19,-169.82 535.92,-173.68 544.22,-177.9 553.19,-177.13 559.08,-176.22 560.41,-176.89 557.76,-178.41 554.1,-179.53 551.05,-181.15 550.34,-184.12 550.12,-186.77
  Top Layer region: 89.58,-184.86 89.14,-182.58 89.4,-180.01 90.29,-179.71 90.89,-181.49 90.46,-183.91
  Top Layer region: 495,-155.05 492.38,-154.24 491.11,-152.31 491.04,-147.91 491.32,-141.18 491.08,-134.41 487.35,-135.18 483.79,-137.5 481.51,-139.74 479.48,-141.28 476.48,-141.92 476.09,-140.37 481.18,-136.25 486.82,-131.97 488.59,-129.62 486.09,-129.63 481.43,-131.01 475.53,-132.08 470.68,-128.58 467.33,-124.67 470.53,-125.5 475.01,-126.62 479.61,-126.94 484.68,-126.1 490.29,-124.42 494.62,-121.98 493.66,-118.99 490.56,-116.36 486.82,-114.5 483.85,-112.96 482.62,-111.13 483.43,-109.69 485.37,-109.1 489.48,-110.42 495.51,-113.59 502.33,-116.82 506.68,-114.68 510.1,-112.28 513.03,-111.28 514.85,-111.9 515.61,-113.39 514.24,-115.61 510.95,-117.98 507.55,-120.63 509.93,-124.08 513.28,-126.5 515.57,-124.47 517.41,-122.62 519.02,-122.69 519.47,-125.41 518.53,-129.9 516.6,-135.67 510.53,-130.91 504.56,-127.6 498.81,-127.57 494.54,-129.66 494.49,-133.81 495.83,-139.63 497.2,-146.84 497.61,-153.45
  Top Layer region: 128.72,-148.48 124.9,-147.62 120.96,-145.55 118.02,-141.6 120.85,-132.38 123.67,-122.99 120.86,-117.86 118.13,-114.01 120.58,-112.17 124.13,-112.02 127.59,-113.58 131.03,-115.14 134.65,-112.71 137.91,-110.35 140.58,-109.8 142.39,-111.4 143.55,-114.19 143.29,-116.6 141.16,-116.64 138.25,-116.66 135.62,-118.36 134.4,-121.29 135.05,-124.25 137.4,-125.96 140.45,-125.88 143.43,-124.94 145.62,-124.57 146.56,-126.18 146.53,-129.98 146.57,-133.8 147.63,-135.42 150.41,-136.72 154.56,-139.74 157.75,-143.41 158.24,-146.29 155.43,-146.51 150.21,-143.07 144.96,-139.16 141.63,-137.54 139.17,-139.15 136.04,-143.01 132.4,-146.87 hole: 71697414.4,61615050.42 71719449.1,61619516.98 71719449.1,61619516.98 71743091.97,61648294.69 71743091.97,61648294.69 71757075.36,61689987.36 71757075.36,61689987.36 71755882.56,61725502.11 71755882.56,61725502.11 71741821.37,61747479.04 71741821.37,61747479.04 71724867.12,61756619.24 71724867.12,61756619.24 71707128.86,61752333.5 71707128.86,61752333.5 71691188.44,61742029.05 71691188.44,61742029.05 71680833.2,61717105.7 71680833.2,61717105.7 71676526.32,61677669.84 71676526.32,61677669.84 71682662.11,61638744.43 71682662.11,61638744.43 71697414.4,61615050.42
  Top Layer region: 451.92,-124.41 449.75,-121.9 447.49,-115.88 444.45,-108.78 438.3,-107.68 433.04,-107.08 430.36,-105.03 430.6,-103.08 433.79,-103.48 437.41,-103.76 439.8,-102.42 440.16,-99.97 438.88,-97.52 437.16,-94.86 436.44,-91.9 437.33,-90.16 440.84,-92.68 444.51,-95.4 445.23,-93.04 444.01,-89.73 441.06,-86.84 439.02,-85.18 439.05,-83.24 441.59,-80.14 447.1,-75 454.6,-68.73 458.25,-66.64 457.51,-68.75 454.41,-72.58 451.03,-76.52 449.63,-78.87 451.61,-80.13 456.38,-81.44 460.91,-83.07 461.61,-85.21 458.72,-86.59 453.76,-86.39 448.33,-86.44 447.51,-93.28 448.49,-100.64 450.73,-106.9 452.97,-112.53 453.95,-118.39 453.39,-122.64
  Top Layer region: 185.92,-118.82 183.92,-118.92 182.03,-117.34 180.04,-113.78 177.79,-109.1 176.53,-103.46 178.5,-97.4 180.98,-93.26 182.52,-92.04 182.6,-94.54 181.59,-99.35 181.07,-105.68 183.9,-111.67 186.22,-116.22
  Top Layer region: 211.09,-108.44 205.4,-107.5 202.42,-105.55 200.22,-103.94 196.31,-103.88 192.6,-104.32 195.34,-102.07 199.61,-98.93 204.13,-95.34 207.09,-92.4 200.74,-94.61 193.75,-96.69 191.3,-94.26 191.67,-89.93 194.62,-84.42 197.56,-79.59 198.03,-76.84 195.94,-77 192.72,-79.2 189.31,-81.76 186.77,-82.83 187.5,-80.7 191.92,-75.58 197.47,-68.33 197.51,-61.02 196.96,-55.74 198.58,-55.26 200.38,-57.63 201.12,-61.12 202.2,-64.3 206.62,-64.03 210.61,-63.68 212.12,-65.01 210.83,-67.35 207.72,-69.7 204.61,-72 203.32,-74.23 204.4,-75.28 207.58,-74.15 211.59,-72.55 215.27,-71.89 217.7,-72.79 218.72,-74.97 217.59,-76.96 214.32,-76.9 210.97,-76.87 209.92,-79.29 210.82,-81.79 212.98,-82.83 215.54,-83.86 217.4,-86.33 216.95,-90.05 213.23,-94.15 209.34,-97.79 207.72,-100.5 209.33,-101.93 213.22,-102.53 217.18,-103.38 218.72,-105.59 216.84,-107.85 hole: 72424593.72,62188831.99 72429058.94,62155739.81 72429058.94,62155739.81 72446249.33,62172418.85 72446249.33,62172418.85 72461405.18,62200423.77 72461405.18,62200423.77 72467904.94,62221658.27 72467904.94,62221658.27 72461682.28,62233250.05 72461682.28,62233250.05 72446249.33,62238071.42 72446249.33,62238071.42 72430816.39,62223607.33 72430816.39,62223607.33 72424593.72,62188831.99 hole: 72380273.07,62128650.47 72395804.98,62135078.95 72395804.98,62135078.95 72402265.16,62150534.66 72402265.16,62150534.66 72395804.98,62165990.37 72395804.98,62165990.37 72380273.07,62172418.85 72380273.07,62172418.85 72364741.16,62165990.37 72364741.16,62165990.37 72358280.99,62150534.66 72358280.99,62150534.66 72364741.16,62135078.95 72364741.16,62135078.95 72380273.07,62128650.47
  Top Layer region: 236.43,-101.36 232.94,-101.72 228.4,-100.23 224.67,-97.7 223.11,-95.59 224.28,-94.31 227.09,-93.77 231.09,-94.64 235.12,-96.72 237.69,-99.39
  Top Layer region: 414.13,-99.05 413.01,-97.41 414.25,-95.28 415.94,-93.04 416.64,-91 415.51,-90.01 412.8,-90.29 409.21,-90.59 405.98,-89.63 405.73,-87.85 411.37,-86.21 418.09,-84.04 422.51,-81.01 424.5,-77.95 425.37,-75.72 423.64,-74.48 419.39,-73.82 416.41,-73.28 422.12,-71.89 429.73,-69.16 435.2,-64.49 438.75,-60.44 441.27,-58.76 442.52,-59.32 443.04,-60.68 442.07,-62.83 439.74,-65.32 437.41,-67.81 436.44,-69.97 437.57,-71.4 440.29,-72.15 441.11,-72.74 437.68,-73.79 434.23,-75.07 431.02,-77.58 427.67,-81.7 423.81,-87.8 417.9,-96.32
  Top Layer region: 257.85,-93.77 255.27,-92.52 260.22,-86.1 263.38,-82.06 266.97,-76.73 270.55,-70.81 273.69,-64.99 278.07,-55.16 279.21,-50.39 276.13,-50.63 270.37,-52.86 264.95,-54.79 262.7,-54.32 265.61,-51.37 272.6,-47.35 279.59,-43.53 282.49,-41.07 281.2,-39.68 278.09,-38.43 274.99,-36.92 273.7,-34.89 274.59,-33.2 276.73,-32.5 279.69,-33.49 282.57,-35.88 286.19,-38.09 291.43,-37.94 296.27,-37.69 299.11,-39.26 298.72,-42.34 294.9,-46.16 289.1,-51.98 283.38,-60.02 279.13,-68.71 281.31,-73.21 283.46,-76.12 283.58,-78.1 281.98,-78.09 280.01,-76.2 277.97,-74.18 276.57,-75.93 273.8,-80.2 268.82,-86.32 262.88,-91.58
  Top Layer region: 373.76,-92.65 368.3,-90.51 363.61,-87.75 361.66,-85.91 362.88,-85.45 365.79,-86.03 369.29,-85.92 371.26,-82.34 372.21,-77.38 372.63,-72.43 371.37,-68.47 366.06,-67.51 360.69,-68.5 359.47,-72.85 358.75,-77.06 357.03,-79.69 355.54,-79.19 356.11,-74.35 356.51,-68.6 352.2,-67.51 347.86,-68.62 345.63,-71.89 344.21,-74.98 342.4,-76.26 341.22,-72.96 341.38,-64.77 342.45,-56.34 343.55,-52.19 344.63,-52.22 345.65,-53.83 347.87,-55.76 351.82,-56.57 355.94,-55.83 358.57,-54.05 358.62,-51.5 356.54,-48.91 354.41,-46.64 354.37,-44.86 355.99,-44.31 359.36,-43.86 363.98,-43.55 369.36,-43.44 379.37,-43.87 384.39,-44.9 384.42,-47.05 382.41,-50.17 380.84,-52.91 379.54,-57.37 378.53,-63.47 377.82,-71.13 376.77,-84.08 375.82,-91.11 hole: 74088586.7,62504911.63 74121313.95,62500681.69 74121313.95,62500681.69 74151093.99,62512121.38 74151093.99,62512121.38 74161632.04,62544450.07 74161632.04,62544450.07 74152732.67,62575361.49 74152732.67,62575361.49 74131335.75,62588218.45 74131335.75,62588218.45 74102745.48,62579591.43 74102745.48,62579591.43 74076546.86,62558849.87 74076546.86,62558849.87 74063498.13,62533878.37 74063498.13,62533878.37 74066522.87,62515081.49 74066522.87,62515081.49 74088586.7,62504911.63 hole: 73884527.91,62418175.01 73926514.65,62413479.76 73926514.65,62413479.76 73966917.96,62419446.21 73966917.96,62419446.21 73974699.31,62435029.12 73974699.31,62435029.12 73960636.2,62450386.35 73960636.2,62450386.35 73945911.67,62456578.48 73945911.67,62456578.48 73925488.45,62450110.61 73925488.45,62450110.61 73897727.01,62435029.12 73897727.01,62435029.12 73884527.91,62418175.01 hole: 74064591.96,62419573.41 74095655.79,62413144.93 74095655.79,62413144.93 74126719.61,62419573.41 74126719.61,62419573.41 74139639.96,62435029.12 74139639.96,62435029.12 74126719.61,62450484.83 74126719.61,62450484.83 74095655.79,62456913.31 74095655.79,62456913.31 74064591.96,62450484.83 74064591.96,62450484.83 74051671.61,62435029.12 74051671.61,62435029.12 74064591.96,62419573.41
  Top Layer region: 307.92,-87.99 304.42,-88.42 299.52,-88.39 293.37,-87.91 279.19,-86.41 290.19,-83.78 298.6,-81.87 303.39,-80.93 305.9,-81.38 308.86,-82.77 310.81,-84.89 309.84,-87.13
  Top Layer region: 175.96,-84.43 173.63,-85.02 171.3,-84.65 170.33,-83.78 171,-81.66 172.61,-78.31 174.91,-75.32 177.24,-74.08 178.52,-75.09 178.27,-77.54 177.32,-80.57 176.93,-83.01
  Top Layer region: 298.66,-75.51 299.92,-72.2 301.59,-67.72 302.29,-63.15 302.93,-60.26 304.48,-59.85 306.04,-62.35 306.68,-66.47 305.41,-70.94 302.12,-74.16
  Top Layer region: 292.84,-71.24 291.29,-71.89 289.74,-71.24 289.09,-69.7 289.74,-68.15 291.29,-67.51 292.84,-68.15 293.49,-69.7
